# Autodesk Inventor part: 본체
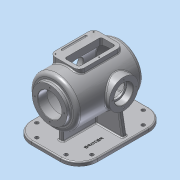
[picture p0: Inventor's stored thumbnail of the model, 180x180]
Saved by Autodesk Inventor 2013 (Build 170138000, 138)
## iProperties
Created: 2016-02
Part Number: 본체
Material: 알루미늄 6061
Document SubType Name: Modeling
Designer: mduedu
Density: 2.71 g/cm^3
Mass: 4129.67 g
Surface Area: 2907.51 cm^2
Volume: 1523.86 cm^3
Author: mduedu
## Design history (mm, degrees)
sketch "스케치2"
  geometry: L1 (0, 100)-(0, -100); L2 (65, -75.993)-(65, 100); L3 (65, 100)-(0, 100); A1 r 100 centre (0, 0) between (0, -100) and (65, -75.993); 2 further points
  constraints: 6 end point, 2 midpoint, 2 point on circle, 1 centre point, 1 coincident, 1 horizontal, 1 parallel, 1 vertical
  dimensions: "d3" = 200 distance of L1.start L1.end; "d5" = 130 diameter of L2 L1; "d6" = 100 radius of A1
revolve "회전1" sketch "스케치2" stored, may be unused: angle "d7" = 90 deg
sketch "스케치3"
  geometry: C1 r 47.5 at (0, 0); 1 further point
  constraints: 1 centre point, 1 coincident
  dimensions: "d8" = 95 diameter of C1
extrude "돌출2" join sketch "스케치3" distance "d10" = 10; taper "d11" = 0 deg
sketch "스케치5"
  geometry: L1 (47.5, 110)-(47.5, 100) reference; L2 (47.5, 100)-(65, 100) reference; L3 (65, 100)-(65, -75.993) reference; L4 (-65, -75.993)-(-65, 100) reference; L5 (-65, 100)-(-47.5, 100) reference; L6 (-47.5, 100)-(-47.5, 110) reference; L7 (-47.5, 110)-(47.5, 110) reference; L8 (55, 85)-(55, -71.239); L9 (0, 85)-(55, 85); L10 (0, 85)-(0, -90); A1 r 100 centre (0, 0) between (0, -100) and (65, -75.993) reference; A2 r 100 centre (0, 0) between (-65, -75.993) and (0, -100) reference; A3 r 90 centre (0, 0) between (0, -90) and (55, -71.239); 1 further point
  constraints: 6 end point, 2 point on circle, 1 centre point, 1 parallel, 1 perpendicular, 1 point on line, 1 vertical
  dimensions: "d13" = 10 distance between parallel lines of L3 L8; "d14" = 10 radial gap between concentric circles of A3 A1; "d15" = 15 distance between parallel lines of L9 L2
revolve "회전2" sketch "스케치5" stored, may be unused: angle "d16" = 90 deg
hole "구멍1" diameter "d19" = 65; stored, may be unused: countersink angle "d23" = 90 deg, drill point angle "d25" = 118 deg; dims "d17" = 10, "d18" = 10, "d20" = 6, "d21" = 4, "d22" = 2, "d24" = 8
node "작업 평면1"
sketch "스케치6"
  geometry: L1 (47.5, 110)-(-47.5, 110) reference; C1 r 40 at (0, -17); 1 further point
  constraints: 1 centre point, 1 vertical alignment
  dimensions: "d27" = 80 diameter of C1; "d29" = 127 distance from line of C1.centre L1
extrude "돌출3" join sketch "스케치6" stored distance "d30" = 10; taper "d31" = 0 deg
hole "구멍2" diameter "d34" = 42; stored, may be unused: countersink angle "d38" = 90 deg, drill point angle "d40" = 118 deg; dims "d32" = 10, "d33" = 10, "d35" = 6, "d36" = 52, "d37" = 18, "d39" = 8
sketch "스케치7" dims "d41" = 65
  geometry: C1 r 40 at (0, 0) reference; 3 further points
  constraints: 2 vertical alignment, 1 coincident, 2 other
hole "구멍3" sketch "스케치7" at (0, 32.5) diameter "d43" = 3.242; stored, may be unused: countersink angle "d47" = 90 deg, drill point angle "d49" = 118 deg; dims "d44" = 11, "d45" = 13, "d46" = 18, "d48" = 13
sketch "스케치8" dims "d53" = 80
  geometry: 3 further points
  constraints: 2 vertical alignment, 1 coincident, 2 other
hole "구멍4" sketch "스케치8" at (0, 40) diameter "d56" = 3.242; stored, may be unused: countersink angle "d60" = 90 deg, drill point angle "d62" = 118 deg; dims "d57" = 11, "d58" = 13, "d59" = 18, "d61" = 13
fillet "모깎기1" dims "d66" = 10
fillet "모깎기2" dims "d67" = 3
fillet "모깎기3" dims "d68" = 0.3
chamfer "모따기1" distance "d69" = 1; stored, may be unused: second distance "d70" = 2, angle "d71" = 45 deg
node "작업 평면5"
sketch "스케치23"
  geometry: L1 (6, 80)-(-6, 80); L2 (-6, 80)-(-6, -60); L3 (-6, -60)-(6, -60); L4 (6, -60)-(6, 80); L5 (-55, 100)-(55, 100) reference; 2 further points
  constraints: 8 end point, 2 parallel, 1 horizontal, 1 midpoint, 1 perpendicular, 1 vertical alignment
  dimensions: "d177" = 12 distance of L1.start L1.end; "d179" = 140 distance of L3.end L1.start; "d180" = 20 distance between parallel lines of L1 L5
extrude "돌출14" join sketch "스케치23" stored distance "d181" = 10; taper "d182" = 0 deg
node "작업 평면6"
sketch "스케치15"
  geometry: L1 (-30, 60)-(50, 60); L2 (50, 60)-(50, -60); L3 (50, -60)-(-30, -60); L4 (-30, -60)-(-30, 60); 3 further points
  constraints: 8 end point, 2 parallel, 1 horizontal, 1 horizontal alignment, 1 midpoint, 1 perpendicular, 1 vertical alignment
  dimensions: "d110" = 80 distance of L2.end L3.end; "d112" = 60 distance from line of L3 point (10, 0); "d113" = 120 distance of L1.end L2.end; "d149" = 30 distance from line of L4 point (0, 0)
extrude "돌출8" join sketch "스케치15" stored distance "d114" = 10; taper "d115" = 0 deg
fillet "모깎기7" dims "d116" = 15
sketch "스케치16"
  geometry: L1 (-30, -45)-(-30, 45) reference; L2 (-15, 60)-(35, 60) reference; L3 (35, -60)-(-15, -60) reference; L4 (-20, -45)-(-20, 45); L5 (-15, 50)-(15, 50); L6 (20, 45)-(20, -45); L7 (15, -50)-(-15, -50); L8 (50, 45)-(50, -45) reference; A1 r 15 centre (-15, -45) between (-30, -45) and (-15, -60) reference; A2 r 15 centre (-15, 45) between (-15, 60) and (-30, 45) reference; A3 r 5 centre (-15, -45) between (-20, -45) and (-15, -50); A4 r 5 centre (-15, 45) between (-15, 50) and (-20, 45); A5 r 5 centre (15, 45) between (20, 45) and (15, 50); A6 r 5 centre (15, -45) between (15, -50) and (20, -45); A7 r 15 centre (35, 45) between (50, 45) and (35, 60) reference; A8 r 15 centre (35, -45) between (35, -60) and (50, -45) reference
  constraints: 8 end point, 8 point on circle, 4 centre point, 2 equal radius, 3 other
  dimensions: "d137" = 10 distance between parallel lines of L4 L1; "d150" = 40 distance between parallel lines of L6 L4; "d151" = 100 distance between parallel lines of L7 L5
extrude "돌출9" cut sketch "스케치16" stored distance "d118" = 10; taper "d119" = 0 deg
fillet "모깎기8" dims "d120" = 3
sketch "스케치17"
  geometry: L1 (-30, -45)-(-30, 45) reference; L2 (-20, 45)-(-20, -45) reference; L3 (-15, -50)-(15, -50) reference; L4 (20, -45)-(20, 45) reference; L5 (15, 50)-(-15, 50) reference; L6 (-15, 60)-(35, 60) reference; L7 (35, -60)-(-15, -60) reference; L8 (15, 55)-(-15, 55); L9 (-25, 45)-(-25, -45); L10 (-15, -55)-(15, -55); L11 (25, -45)-(25, 45); L12 (50, 45)-(50, -45) reference; L13 (35, 55)-(-15, 55); L14 (-25, 45)-(-25, -45); L15 (-15, -55)-(35, -55); L16 (45, -45)-(45, 45); A1 r 5 centre (-15, 45) between (-15, 50) and (-20, 45) reference; A2 r 5 centre (-15, -45) between (-20, -45) and (-15, -50) reference; A3 r 5 centre (15, -45) between (15, -50) and (20, -45) reference; A4 r 5 centre (15, 45) between (20, 45) and (15, 50) reference; A5 r 15 centre (-15, 45) between (-15, 60) and (-30, 45) reference; A6 r 15 centre (-15, -45) between (-30, -45) and (-15, -60) reference; A7 r 10 centre (-15, 45) between (-15, 55) and (-25, 45); A8 r 10 centre (-15, -45) between (-25, -45) and (-15, -55); A9 r 10 centre (15, -45) between (15, -55) and (25, -45); A10 r 10 centre (15, 45) between (25, 45) and (15, 55); A11 r 15 centre (35, 45) between (50, 45) and (35, 60) reference; A12 r 15 centre (35, -45) between (35, -60) and (50, -45) reference; A13 r 10 centre (-15, 45) between (-15, 55) and (-25, 45); A14 r 10 centre (-15, -45) between (-25, -45) and (-15, -55); A15 r 10 centre (35, -45) between (35, -55) and (45, -45); A16 r 10 centre (35, 45) between (45, 45) and (35, 55); 6 further points
  constraints: 18 point on circle, 16 end point, 8 centre point, 4 midpoint, 4 tangent, 11 other
  dimensions: "d138" = 5 distance between parallel lines of L8 L6; "d157" = 5 distance between parallel lines of L12 L16
hole "구멍5" sketch "스케치17" at (-25, 0), (42.071, 52.071), (42.071, -52.071) diameter "d122" = 3.242; stored, may be unused: countersink angle "d126" = 90 deg, drill point angle "d128" = 118 deg; dims "d123" = 9, "d124" = 13, "d125" = 18, "d127" = 11
sketch "스케치19"
  geometry: L1 (-50, 70)-(-35, 70) reference; L2 (-50, 42.603)-(-50, 70) reference; C1 r 2.5 at (-43, 70); 1 further point
  constraints: 1 centre point, 1 point on line
  dimensions: "d152" = 5 diameter of C1; "d153" = 7 distance from line of C1.centre L2
extrude "돌출11" cut sketch "스케치19" stored distance "d154" = 70; taper "d155" = 0 deg
fillet "모깎기11" dims "d156" = 2.5
sketch "스케치20"
  geometry: L1 (-90, 120)-(90, 120); L2 (90, 120)-(90, -120); L3 (90, -120)-(-90, -120); L4 (-90, -120)-(-90, 120); 3 further points
  constraints: 8 end point, 2 parallel, 2 vertical alignment, 1 coincident, 1 horizontal, 1 midpoint, 1 perpendicular
  dimensions: "d162" = 180 distance of L1.start L1.end; "d164" = 240 distance of L1.end L2.end; "d165" = 120 distance from line of L1 point (0, 0)
extrude "돌출12" join sketch "스케치20" distance "d166" = 10; taper "d167" = 0 deg
fillet "모깎기12" dims "d168" = 50
node "작업 평면8"
  node "작업축1"
sketch "스케치24"
  geometry: L1 (128, 34.121)-(127.026, 32.5) reference; L2 (127.026, 32.5)-(128, 30.879) reference; L3 (128, 30.879)-(141, 30.879) reference; L4 (141, 30.879)-(141, 27) reference; L5 (141, 27)-(140, 26) reference; L6 (140, 26)-(123.3, 26) reference; L7 (123, 25.7)-(123, 21) reference; L8 (123, 21)-(116.833, 21) reference; L9 (86, 51.235)-(86, 70) reference; L10 (86, 70)-(106.5, 70) reference; L11 (111.5, 70)-(116, 70) reference; L12 (116, 70)-(116, 42.603) reference; L13 (118.678, 40)-(141, 40) reference; L14 (141, 40)-(141, 34.121) reference; L15 (141, 34.121)-(128, 34.121) reference; L16 (4, -34.121)-(4.974, -32.5) reference; L17 (4.974, -32.5)-(4, -30.879) reference; L18 (4, -30.879)-(-9, -30.879) reference; L19 (-9, -30.879)-(-9, -27) reference; L20 (-9, -27)-(-8, -26) reference; L21 (-8, -26)-(8.7, -26) reference; L22 (9, -25.7)-(9, -21) reference; L23 (9, -21)-(15.167, -21) reference; L24 (116.833, -21)-(123, -21) reference; L25 (123, -21)-(123, -25.7) reference; L26 (123.3, -26)-(140, -26) reference; L27 (140, -26)-(141, -27) reference; L28 (141, -27)-(141, -30.879) reference; L29 (141, -30.879)-(128, -30.879) reference; L30 (128, -30.879)-(127.026, -32.5) reference; L31 (127.026, -32.5)-(128, -34.121) reference; L32 (128, -34.121)-(141, -34.121) reference; L33 (141, -34.121)-(141, -40) reference; L34 (141, -40)-(118.678, -40) reference; L35 (72, -64.722)-(72, -100) reference; L36 (72, -100)-(156, -100) reference; L37 (156, -100)-(156, -110) reference; L38 (156, -110)-(-24, -110) reference; L39 (-24, -110)-(-24, -100) reference; L40 (-24, -100)-(60, -100) reference; L41 (60, -100)-(60, -64.722) reference; L42 (13.322, -40)-(-9, -40) reference; L43 (-9, -40)-(-9, -34.121) reference; L44 (-9, -34.121)-(4, -34.121) reference; L45 (4.974, 32.5)-(4, 34.121) reference; L46 (4, 34.121)-(-9, 34.121) reference; L47 (-9, 34.121)-(-9, 40) reference; L48 (-9, 40)-(13.322, 40) reference; L49 (36, 59.456)-(36, 70) reference; L50 (36, 70)-(46, 70) reference; L51 (46, 70)-(46, 51.235) reference; L52 (15.167, 21)-(9, 21) reference; L53 (9, 21)-(9, 25.7) reference; L54 (8.7, 26)-(-8, 26) reference; L55 (-8, 26)-(-9, 27) reference; L56 (-9, 27)-(-9, 30.879) reference; L57 (-9, 30.879)-(4, 30.879) reference; L58 (4, 30.879)-(4.974, 32.5) reference; L59 (-1, -40)-(-11.58, -100); A1 r 0.3 centre (123.3, 25.7) between (123.3, 26) and (123, 25.7) reference; A2 r 55 centre (66, 0) between (116.833, 21) and (86, 51.235) reference; A3 r 2.5 centre (109, 70) between (106.5, 70) and (111.5, 70) reference; A4 r 3 centre (119, 42.603) between (116, 42.603) and (116.516, 40.92) reference; A5 r 0.3 centre (8.7, -25.7) between (8.7, -26) and (9, -25.7) reference; A6 r 55 centre (66, 0) between (15.167, -21) and (116.833, -21) reference; A7 r 0.3 centre (123.3, -25.7) between (123, -25.7) and (123.3, -26) reference; A8 r 65 centre (66, 0) between (72, -64.722) and (116.354, -41.103) reference; A9 r 65 centre (66, 0) between (15.646, -41.103) and (60, -64.722) reference; A10 r 65 centre (66, 0) between (34.456, 56.833) and (15.646, 41.103) reference; A11 r 3 centre (33, 59.456) between (34.456, 56.833) and (36, 59.456) reference; A12 r 55 centre (66, 0) between (46, 51.235) and (15.167, 21) reference; A13 r 0.3 centre (8.7, 25.7) between (9, 25.7) and (8.7, 26) reference; 1 further point
  constraints: 2 end point, 2 point on line, 4 other
  dimensions: "d184" = 8 distance of L59.start L42.end; "d185" = 100 deg angle of L59 L40
feature "리브2" sketch "스케치24" dims "d186" = 1, "d187" = 12, "d188" = 0, "d189" = 0, "d190" = 1, "d191" = 1
fillet "모깎기15" dims "d192" = 3
fillet "모깎기16" dims "d193" = 3
sketch "스케치25"
  geometry: L1 (90, -70)-(90, 70) reference; L2 (40, 120)-(-40, 120) reference; L3 (-90, 70)-(-90, -70) reference; L4 (-40, -120)-(40, -120) reference; L5 (-74.004, 8)-(-9, 8) reference; L6 (-80.097, 20)-(-80.097, 14) reference; L7 (-9, 26)-(-74.004, 26) reference; L8 (-9, 57)-(-9, 26) reference; L9 (3, 63)-(-3, 63) reference; L10 (9, 26)-(9, 57) reference; L11 (74.004, 26)-(9, 26) reference; L12 (80.097, 14)-(80.097, 20) reference; L13 (9, 8)-(74.004, 8) reference; L14 (9, -77)-(9, 8) reference; L15 (-3, -83)-(3, -83) reference; L16 (-9, 8)-(-9, -77) reference; L17 (-40, 105)-(40, 105); L18 (75, 70)-(75, -70); L19 (40, -105)-(-40, -105); L20 (-75, -70)-(-75, 70); C1 r 5 at (-75, 70); C2 r 5 at (-40, 105); C3 r 5 at (40, 105); C4 r 5 at (75, 70); C5 r 5 at (75, -70); C6 r 5 at (40, -105); C7 r 5 at (-40, -105); C8 r 5 at (-75, -70); A1 r 50 centre (40, 70) between (90, 70) and (40, 120) reference; A2 r 50 centre (-40, 70) between (-40, 120) and (-90, 70) reference; A3 r 50 centre (-40, -70) between (-90, -70) and (-40, -120) reference; A4 r 50 centre (40, -70) between (40, -120) and (90, -70) reference; A5 r 6 centre (-3, 57) between (-3, 63) and (-9, 57) reference; A6 r 6 centre (3, 57) between (9, 57) and (3, 63) reference; A7 r 6 centre (3, -77) between (3, -83) and (9, -77) reference; A8 r 6 centre (-3, -77) between (-9, -77) and (-3, -83) reference; A9 r 35 centre (40, 70) between (75, 70) and (40, 105); A10 r 35 centre (40, -70) between (40, -105) and (75, -70); A11 r 35 centre (-40, -70) between (-75, -70) and (-40, -105); A12 r 35 centre (-40, 70) between (-40, 105) and (-75, 70); 5 further points; 4 other entities
  constraints: 12 centre point, 8 coincident, 8 end point, 8 point on circle, 7 equal radius, 11 other
  dimensions: "d194" = 15 distance between parallel lines of L17 L2; "d195" = 10 diameter of C1
extrude "돌출15" cut sketch "스케치25" stored distance "d197" = 10; taper "d198" = 0 deg
fillet "모깎기14" dims "d170" = 3
sketch "스케치22"
  geometry: L1 (90, -70)-(90, 70) reference; 2 further points
  constraints: 1 other
  dimensions: "d174" = 40 distance from line of L1 point (50, -40); "d199" = 40 vertical distance of point (50, -40) point (0, 0)
feature "엠보싱2" sketch "스케치22" dims "d13" = 10, "d175" = 0.5, "d176" = 0
node "솔리드2"
pattern_circular "원형 패턴1" dims angle "d51" = 360 deg
mirror "대칭1"
pattern_circular "원형 패턴2" dims angle "d64" = 360 deg
mirror "대칭3"
node "투영된 루프2"
node "절단 모서리 투영1"
node "절단 모서리 투영2"
node "절단 모서리 투영3"
node "절단 모서리 투영4"
other parameters: "d26" = 75, "d183" = 0
